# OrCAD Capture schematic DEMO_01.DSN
size A
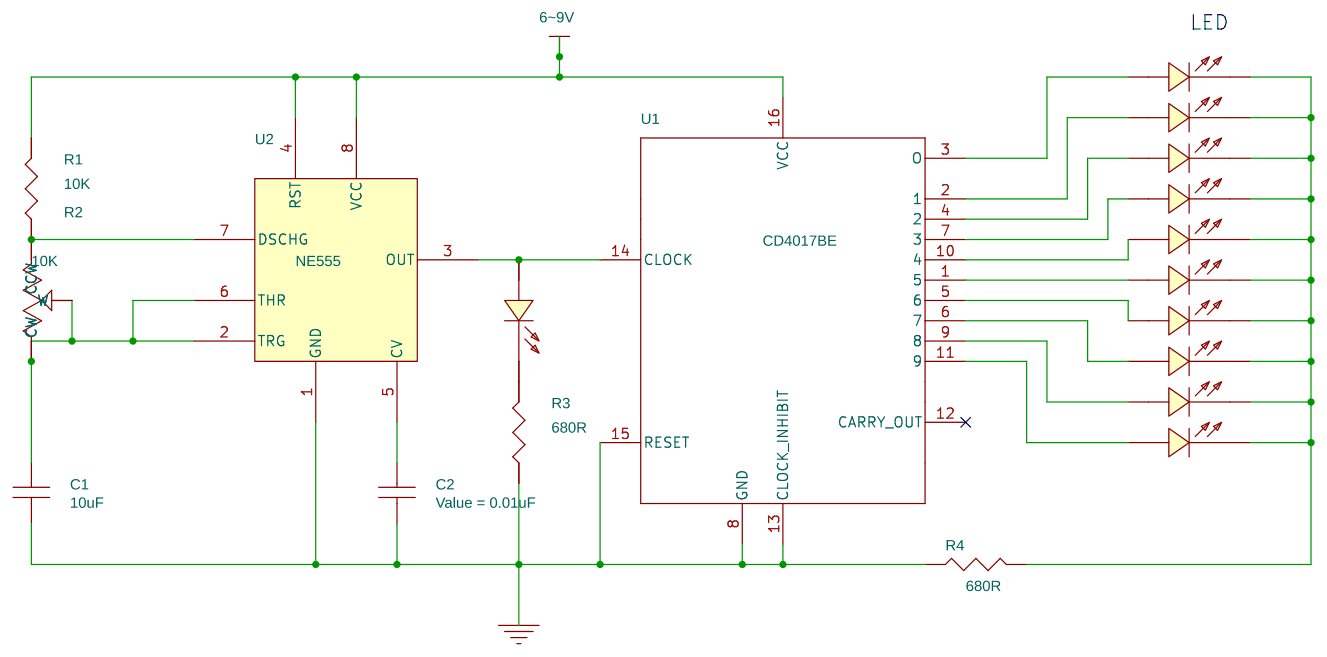
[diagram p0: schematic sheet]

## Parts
C1  10uF  [cap_disk_2p_252]
C2  0.01uF  [cap_disk_2p_252]
D1  LED  [LED_3mm]
D2  LED  [LED_3mm]
D3  LED  [LED_3mm]
D4  LED  [LED_3mm]
D5  LED  [LED_3mm]
D6  LED  [LED_3mm]
D7  LED  [LED_3mm]
D8  LED  [LED_3mm]
D9  LED  [LED_3mm]
D10  LED  [LED_3mm]
D11  LED  [LED_3mm]
R1  10K  [resisitor_th]
R2  10K  [TRIM_3306K-1-103]
R3  680R  [resisitor_th]
R4  680R  [resisitor_th]
U1  CD4017BE  [DIP794W45P254L1969H508Q16]
U2  NE555  [DIP794W45P254L959H508Q8]

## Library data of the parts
C1 C2 = CAP_NP
D1-D11 = LED
R1 R3 R4 = R
R2 = 3306K-1-103
U1 = CD4017BE_7
U2 = NE555_4

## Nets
GND: C1.2 C2.2 R3.1 R4.1 U1.8(GND) U1.13(CLOCK_INHIBIT) U1.15(RESET) U2.1(GND)
6~9V: R1.2 U1.16(VCC) U2.4(RST) U2.8(VCC)
N00554: D1.2(ANODE) U1.3(O)
N00566: D2.2(ANODE) U1.2(1)
N00584: D3.2(ANODE) U1.4(2)
N00596: D4.2(ANODE) U1.7(3)
N00608: D5.2(ANODE) U1.10(4)
N00623: D6.2(ANODE) U1.1(5)
N00627: D8.2(ANODE) U1.5(6)
N00642: D9.2(ANODE) U1.6(7)
N00654: D10.2(ANODE) U1.9(8)
N00672: D11.2(ANODE) U1.11(9)
N00724: D1.1(CATHODE) D2.1(CATHODE) D3.1(CATHODE) D4.1(CATHODE) D5.1(CATHODE) D6.1(CATHODE) D8.1(CATHODE) D9.1(CATHODE) D10.1(CATHODE) D11.1(CATHODE) R4.2
N03868: D7.2(ANODE) U1.14(CLOCK) U2.3(OUT)
N03928: C2.1 U2.5(CV)
N04007: R1.1 R2.1(CCW) U2.7(DSCHG)
N04040: C1.1 R2.2(W) R2.3(CW) U2.2(TRG) U2.6(THR)
N06006: D7.1(CATHODE) R3.2

Not connected (* = marked no-connect by the designer): U1 12(CARRY_OUT)*

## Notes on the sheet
- LED
